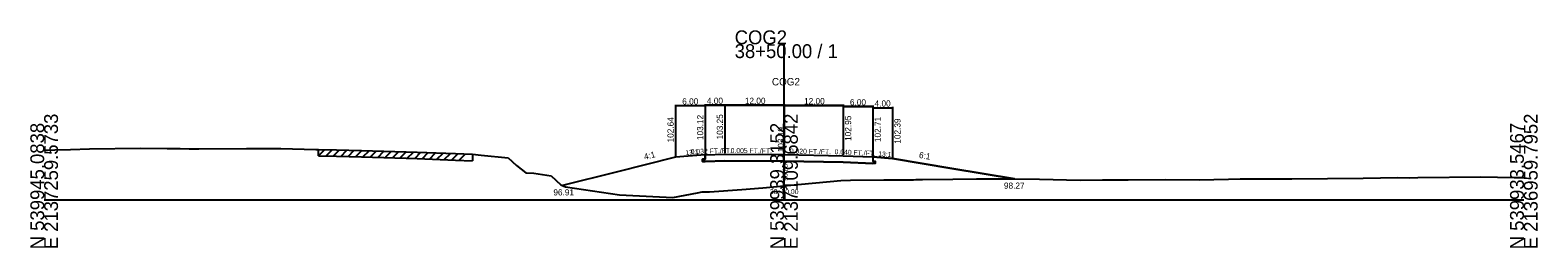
# Model space of a CAD drawing. Extents: x -13397 to 2303, y -10 to 39059.
# Drawn here: x 997.2 to 1302.8, y 16990.3 to 17034.4 of the extents above; entities that cross this region are included whole.
import ezdxf

# ---------------------------------------------------------------- set-up
doc = ezdxf.new("R2010")
doc.units = 0
for name, color, linetype in [('Level 5', 7, 'Continuous'), ('Level 53', 7, 'Continuous'), ('Level 54', 7, 'Continuous'), ('Level 55', 7, 'Continuous'), ('Level 7', 7, 'Continuous'), ('RD_GPK_XS_Cell', 7, 'Continuous'), ('RD_XS_EwShp', 7, 'Continuous'), ('RD_XS_ExGround', 7, 'Continuous'), ('RD_XS_ExPaveRet', 7, 'Continuous'), ('RD_XS_Pave', 7, 'Continuous'), ('RD_XS_TX_Baseline', 7, 'Continuous'), ('RD_XS_TX_Elev_EX', 7, 'Continuous'), ('RD_XS_TX_Elev_PR', 7, 'Continuous'), ('RD_XS_TX_Station', 7, 'Continuous')]:
    doc.layers.add(name, color=color, linetype=linetype)

msp = doc.modelspace()

# ---------------------------------------------------------------- linework, layer by layer
at = {"layer": 'Level 5'}
for p, q in [((1134, 17008.29), (1133.5, 17008.27)), ((1133.5, 17008.27), (1133.5, 17007.77)), ((1134, 17009.12), (1134, 17008.29)), ((1168, 17008.71), (1168, 17007.88)), ((1133.5, 17007.77), (1134, 17007.79)), ((1138, 17007.92), (1134, 17007.79)), ((1138, 17007.92), (1134, 17007.79)), ((1138, 17007.92), (1134, 17007.79)), ((1134, 17007.79), (1138, 17007.92)), ((1150, 17007.86), (1138, 17007.92)), ((1150, 17007.86), (1138, 17007.92)), ((1150, 17007.86), (1138, 17007.92)), ((1138, 17007.92), (1150, 17007.86)), ((1138, 17007.92), (1150, 17007.86)), ((1162, 17007.62), (1150, 17007.86)), ((1162, 17007.62), (1150, 17007.86)), ((1150, 17007.86), (1162, 17007.62)), ((1150, 17007.86), (1162, 17007.62)), ((1150, 17007.86), (1162, 17007.62)), ((1168, 17007.38), (1162, 17007.62)), ((1162, 17007.62), (1168, 17007.38)), ((1162, 17007.62), (1168, 17007.38)), ((1162, 17007.62), (1168, 17007.38)), ((1168, 17007.88), (1168.5, 17007.86)), ((1168.5, 17007.36), (1168, 17007.38)), ((1168.5, 17007.86), (1168.5, 17007.36))]:
    msp.add_line(p, q, dxfattribs=at)
at = {"layer": 'Level 54'}
for p, q in [((1128, 17019.27), (1128, 17008.84)), ((1134, 17019.07), (1128, 17019.07)), ((1134, 17019.4), (1134, 17009.32)), ((1134, 17019.4), (1134, 17009.32)), ((1134, 17019.4), (1134, 17009.32)), ((1134, 17019.4), (1134, 17009.32)), ((1134, 17019.27), (1134, 17009.32)), ((1134, 17019.2), (1138, 17019.2)), ((1134, 17019.2), (1138, 17019.2)), ((1134, 17019.2), (1138, 17019.2)), ((1138, 17019.2), (1134, 17019.2)), ((1138, 17019.4), (1138, 17009.45)), ((1138, 17019.4), (1138, 17009.45)), ((1138, 17019.4), (1138, 17009.45)), ((1138, 17019.4), (1138, 17009.45)), ((1138, 17019.4), (1138, 17009.45)), ((1138, 17019.4), (1138, 17009.45)), ((1138, 17019.4), (1138, 17009.45)), ((1138, 17019.4), (1138, 17009.45)), ((1138, 17019.4), (1138, 17009.45)), ((1138, 17019.2), (1150, 17019.2)), ((1138, 17019.2), (1150, 17019.2)), ((1138, 17019.2), (1150, 17019.2)), ((1150, 17019.2), (1138, 17019.2)), ((1150, 17019.2), (1138, 17019.2)), ((1150, 17019.4), (1150, 17009.39)), ((1150, 17019.4), (1150, 17009.39)), ((1150, 17019.4), (1150, 17009.39)), ((1150, 17019.4), (1150, 17009.39)), ((1150, 17019.4), (1150, 17009.39)), ((1150, 17019.34), (1150, 17009.39)), ((1150, 17019.34), (1150, 17009.39)), ((1150, 17019.34), (1150, 17009.39)), ((1150, 17019.34), (1150, 17009.39)), ((1150, 17019.34), (1150, 17009.39)), ((1150, 17019.14), (1162, 17019.14)), ((1150, 17019.14), (1162, 17019.14)), ((1162, 17019.14), (1150, 17019.14)), ((1162, 17019.14), (1150, 17019.14)), ((1162, 17019.14), (1150, 17019.14)), ((1162, 17019.34), (1162, 17009.15)), ((1162, 17019.34), (1162, 17009.15)), ((1162, 17019.34), (1162, 17009.15)), ((1162, 17019.34), (1162, 17009.15)), ((1162, 17019.34), (1162, 17009.15)), ((1162, 17019.1), (1162, 17009.15)), ((1162, 17019.1), (1162, 17009.15)), ((1162, 17019.1), (1162, 17009.15)), ((1162, 17019.1), (1162, 17009.15)), ((1162, 17018.9), (1168, 17018.9)), ((1168, 17018.9), (1162, 17018.9)), ((1168, 17018.9), (1162, 17018.9)), ((1168, 17018.9), (1162, 17018.9)), ((1168, 17019.1), (1168, 17008.91)), ((1168, 17019.1), (1168, 17008.91)), ((1168, 17019.1), (1168, 17008.91)), ((1168, 17019.1), (1168, 17008.91)), ((1168, 17018.86), (1168, 17008.91)), ((1168, 17018.66), (1172, 17018.66)), ((1172, 17018.86), (1172, 17008.59))]:
    msp.add_line(p, q, dxfattribs=at)
at = {"layer": 'Level 7'}
for p, q in [((1128, 17008.64), (1116, 17005.64)), ((1134, 17009.12), (1128, 17008.64)), ((1168, 17008.71), (1172, 17008.39)), ((1172, 17008.39), (1184, 17006.39)), ((1116, 17005.64), (1105.08, 17002.91)), ((1184, 17006.39), (1196.73, 17004.27))]:
    msp.add_line(p, q, dxfattribs=at)
at = {"layer": 'RD_GPK_XS_Cell'}
for p, q in [((1150, 17000), (1150, 17031.53)), ((1000, 17000), (1150, 17000)), ((1150, 17000), (1300, 17000))]:
    msp.add_line(p, q, dxfattribs=at)
at = {"layer": 'RD_XS_EwShp'}
msp.add_lwpolyline([(1128, 17008.64), (1116, 17005.64), (1105.08, 17002.91), (1105.73, 17002.64), (1116.68, 17001.04), (1127.43, 17000.52), (1132.48, 17001.42), (1133.44, 17001.62), (1134.87, 17001.67), (1141.46, 17002.14), (1145.7, 17002.45), (1150, 17002.85), (1150.67, 17002.91), (1161.49, 17003.93), (1163.45, 17004.01), (1170.26, 17004.05), (1176.24, 17004.1), (1176.76, 17004.11), (1178.11, 17004.12), (1184.21, 17004.24), (1189.02, 17004.25), (1194.27, 17004.3), (1196.73, 17004.27), (1184, 17006.39), (1172, 17008.39), (1168, 17008.71), (1168, 17007.88), (1168.5, 17007.86), (1168.5, 17007.36), (1168, 17007.38), (1162, 17007.62), (1150, 17007.86), (1138, 17007.92), (1134, 17007.79), (1133.5, 17007.77), (1133.5, 17008.27), (1134, 17008.29), (1134, 17009.12)], close=True, dxfattribs=at)
at = {"layer": 'RD_XS_ExGround'}
for p, q in [((1000, 17010.07), (1002.18, 17010.14)), ((1002.18, 17010.14), (1005.33, 17010.22)), ((1005.33, 17010.22), (1009.22, 17010.34)), ((1009.22, 17010.34), (1019.56, 17010.51)), ((1019.56, 17010.51), (1024.95, 17010.44)), ((1024.95, 17010.44), (1027.6, 17010.41)), ((1027.6, 17010.41), (1029.38, 17010.35)), ((1029.38, 17010.35), (1029.74, 17010.35)), ((1029.74, 17010.35), (1031.36, 17010.33)), ((1031.36, 17010.33), (1041.01, 17010.45)), ((1041.01, 17010.45), (1047.99, 17010.39)), ((1047.99, 17010.39), (1055.1, 17010.24)), ((1055.1, 17010.24), (1055.62, 17010.22)), ((1055.62, 17010.22), (1059.3, 17010.15)), ((1059.3, 17010.15), (1064.33, 17010.01)), ((1064.33, 17010.01), (1075.65, 17009.68)), ((1075.65, 17009.68), (1083.37, 17009.38)), ((1083.37, 17009.38), (1086.87, 17009.24)), ((1086.87, 17009.24), (1088.58, 17009.08)), ((1088.58, 17009.08), (1094.06, 17008.5)), ((1094.06, 17008.5), (1095.74, 17006.96)), ((1095.74, 17006.96), (1097.65, 17005.49)), ((1097.65, 17005.49), (1099.28, 17005.45)), ((1099.28, 17005.45), (1102.77, 17004.89)), ((1102.77, 17004.89), (1104.77, 17003.04)), ((1104.77, 17003.04), (1105.73, 17002.64)), ((1105.73, 17002.64), (1116.68, 17001.04)), ((1134.87, 17001.67), (1141.46, 17002.14)), ((1141.46, 17002.14), (1145.7, 17002.45)), ((1145.7, 17002.45), (1150, 17002.85)), ((1150, 17002.85), (1150.67, 17002.91)), ((1150.67, 17002.91), (1161.49, 17003.93)), ((1161.49, 17003.93), (1163.45, 17004.01)), ((1163.45, 17004.01), (1170.26, 17004.05)), ((1170.26, 17004.05), (1176.24, 17004.1)), ((1176.24, 17004.1), (1176.76, 17004.11)), ((1176.76, 17004.11), (1178.11, 17004.12)), ((1178.11, 17004.12), (1184.21, 17004.24)), ((1184.21, 17004.24), (1189.02, 17004.25)), ((1189.02, 17004.25), (1194.27, 17004.3)), ((1194.27, 17004.3), (1201.8, 17004.19)), ((1201.8, 17004.19), (1210.04, 17004)), ((1210.04, 17004), (1214.59, 17004.05)), ((1214.59, 17004.05), (1219.77, 17004.06)), ((1219.77, 17004.06), (1227.37, 17004.11)), ((1227.37, 17004.11), (1234.17, 17004.07)), ((1234.17, 17004.07), (1240.15, 17004.2)), ((1240.15, 17004.2), (1242.49, 17004.26)), ((1242.49, 17004.26), (1252.94, 17004.27)), ((1252.94, 17004.27), (1267.41, 17004.4)), ((1267.41, 17004.4), (1274.47, 17004.54)), ((1274.47, 17004.54), (1276.72, 17004.51)), ((1276.72, 17004.51), (1278.5, 17004.55)), ((1278.5, 17004.55), (1291.29, 17004.65)), ((1291.29, 17004.65), (1298.02, 17004.53)), ((1298.02, 17004.53), (1300, 17004.57)), ((1116.68, 17001.04), (1127.43, 17000.52)), ((1127.43, 17000.52), (1132.48, 17001.42)), ((1132.48, 17001.42), (1133.44, 17001.62)), ((1133.44, 17001.62), (1134.87, 17001.67))]:
    msp.add_line(p, q, dxfattribs=at)
at = {"layer": 'RD_XS_ExPaveRet'}
for p, q in [((1055.62, 17008.92), (1055.62, 17010.22)), ((1055.62, 17008.92), (1056.89, 17010.2)), ((1055.62, 17008.92), (1059.3, 17008.85)), ((1057.12, 17008.89), (1058.39, 17010.17)), ((1058.62, 17008.86), (1059.89, 17010.13)), ((1059.3, 17008.85), (1064.33, 17008.71)), ((1060.12, 17008.83), (1061.38, 17010.09)), ((1061.62, 17008.79), (1062.88, 17010.05)), ((1063.12, 17008.74), (1064.38, 17010.01)), ((1064.33, 17008.71), (1075.65, 17008.38)), ((1064.62, 17008.7), (1065.88, 17009.96)), ((1066.12, 17008.66), (1067.38, 17009.92)), ((1067.62, 17008.61), (1068.88, 17009.88)), ((1069.12, 17008.57), (1070.38, 17009.83)), ((1070.62, 17008.53), (1071.88, 17009.79)), ((1072.12, 17008.48), (1073.38, 17009.74)), ((1073.62, 17008.44), (1074.88, 17009.7)), ((1075.12, 17008.39), (1076.38, 17009.65)), ((1075.65, 17008.38), (1083.37, 17008.08)), ((1076.62, 17008.34), (1077.87, 17009.59)), ((1078.12, 17008.28), (1079.37, 17009.54)), ((1079.62, 17008.23), (1080.87, 17009.48)), ((1081.12, 17008.17), (1082.38, 17009.42)), ((1082.62, 17008.11), (1083.87, 17009.36)), ((1084.12, 17008.05), (1085.37, 17009.3)), ((1086.87, 17009.24), (1086.87, 17007.94)), ((1083.37, 17008.08), (1086.87, 17007.94))]:
    msp.add_line(p, q, dxfattribs=at)
at = {"layer": 'RD_XS_Pave'}
for p, q in [((1134, 17009.12), (1138, 17009.25)), ((1138, 17009.25), (1150, 17009.19)), ((1150, 17009.19), (1162, 17008.95)), ((1162, 17008.95), (1168, 17008.71))]:
    msp.add_line(p, q, dxfattribs=at)

# ---------------------------------------------------------------- texts
at = {"layer": 'Level 53'}
for s, rotation, p in [('103.25', 90, (1137.62, 17012.25)), ('103.25', 90, (1137.62, 17012.25)), ('103.25', 90, (1137.62, 17012.25)), ('102.64', 90, (1127.62, 17011.64)), ('103.12', 90, (1133.62, 17012.12)), ('102.95', 90, (1163.62, 17011.95)), ('102.95', 90, (1163.62, 17011.95)), ('102.95', 90, (1163.62, 17011.95)), ('102.71', 90, (1169.62, 17011.71)), ('102.39', 90, (1173.62, 17011.39)), ('4:1', 14.0362, (1121.76, 17008.11)), ('6:1', 350.5377, (1177.3, 17008.52))]:
    msp.add_text(s, height=1.25, rotation=rotation, dxfattribs=at).set_placement(p)
for s, p in [('96.91', (1103.24, 17000.91)), ('98.27', (1194.59, 17002.27))]:
    msp.add_text(s, height=1.25, dxfattribs=at).set_placement(p)
at = {"layer": 'Level 54'}
for s, p in [('6.00', (1129.37, 17019.32)), ('4.00', (1134.37, 17019.45)), ('4.00', (1134.37, 17019.45)), ('4.00', (1134.37, 17019.45)), ('4.00', (1134.37, 17019.45)), ('12.00', (1142.07, 17019.45)), ('12.00', (1142.07, 17019.45)), ('12.00', (1142.07, 17019.45)), ('12.00', (1142.07, 17019.45)), ('12.00', (1142.07, 17019.45)), ('12.00', (1154.07, 17019.39)), ('12.00', (1154.07, 17019.39)), ('12.00', (1154.07, 17019.39)), ('12.00', (1154.07, 17019.39)), ('12.00', (1154.07, 17019.39)), ('6.00', (1163.37, 17019.15)), ('6.00', (1163.37, 17019.15)), ('6.00', (1163.37, 17019.15)), ('6.00', (1163.37, 17019.15)), ('4.00', (1168.37, 17018.91))]:
    msp.add_text(s, height=1.25, dxfattribs=at).set_placement(p)
at = {"layer": 'Level 55'}
for s, rotation, p in [('13:1', 4.5739, (1130.03, 17009.06)), ('0.032 FT./FT.', 1.8436, (1131.1, 17009.28)), ('0.032 FT./FT.', 1.8436, (1131.1, 17009.28)), ('0.032 FT./FT.', 1.8436, (1131.1, 17009.28)), ('0.032 FT./FT.', 1.8436, (1131.1, 17009.28)), ('0.005 FT./FT.', 359.7016, (1139.18, 17009.5)), ('0.005 FT./FT.', 359.7016, (1139.18, 17009.5)), ('0.005 FT./FT.', 359.7016, (1139.18, 17009.5)), ('0.005 FT./FT.', 359.7016, (1139.18, 17009.5)), ('0.005 FT./FT.', 359.7016, (1139.18, 17009.5)), ('0.020 FT./FT.', 358.8542, (1151.18, 17009.42)), ('0.020 FT./FT.', 358.8542, (1151.18, 17009.42)), ('0.020 FT./FT.', 358.8542, (1151.18, 17009.42)), ('0.020 FT./FT.', 358.8542, (1151.18, 17009.42)), ('0.020 FT./FT.', 358.8542, (1151.18, 17009.42)), ('0.040 FT./FT.', 357.7094, (1160.24, 17009.27)), ('0.040 FT./FT.', 357.7094, (1160.24, 17009.27)), ('0.040 FT./FT.', 357.7094, (1160.24, 17009.27)), ('0.040 FT./FT.', 357.7094, (1160.24, 17009.27)), ('13:1', 355.4261, (1169.07, 17008.88))]:
    msp.add_text(s, height=1, rotation=rotation, dxfattribs=at).set_placement(p)
at = {"layer": 'RD_GPK_XS_Cell'}
for s, p in [('COG2', (1140, 17031.53)), ('38+50.00 / 1', (1140, 17028.73))]:
    msp.add_text(s, height=2.8, dxfattribs=at).set_placement(p)
for s, p in [('E 2137259.5733', (1002.8, 16990)), ('E 2137109.6842', (1152.8, 16990)), ('E 2136959.7952', (1302.8, 16990)), ('N 539945.0838', (1000, 16990)), ('N 539939.3152', (1150, 16990)), ('N 539933.5467', (1300, 16990))]:
    msp.add_text(s, height=2.8, rotation=90, dxfattribs=at).set_placement(p)
at = {"layer": 'RD_XS_TX_Baseline'}
msp.add_text('COG2', height=1.5, dxfattribs=at).set_placement((1147.55, 17023.19))
at = {"layer": 'RD_XS_TX_Elev_EX'}
msp.add_text('96.85', height=1, rotation=90, dxfattribs=at).set_placement((1150.75, 17003.85))
at = {"layer": 'RD_XS_TX_Elev_PR'}
msp.add_text(' 103.19', height=1.25, rotation=90, dxfattribs=at).set_placement((1150, 17009.19))
at = {"layer": 'RD_XS_TX_Station'}
msp.add_text('38+50.00', height=1, dxfattribs=at).set_placement((1147.14, 17001.19))

doc.saveas('drawing.dxf')
